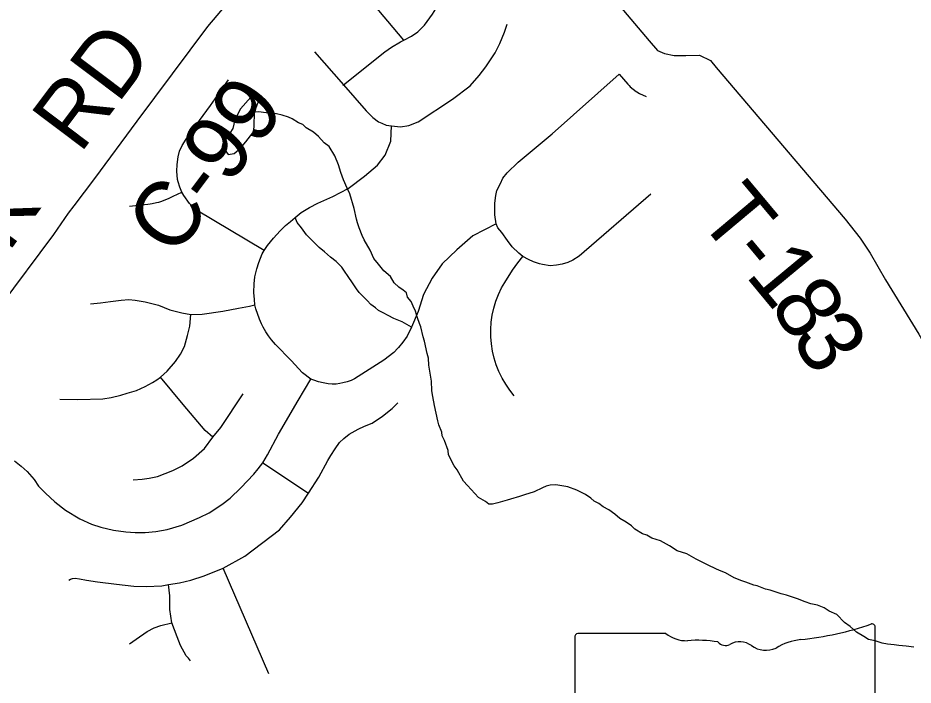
# Model space of a CAD drawing. Extents: x 0 to 34, y 0 to 22.
# Drawn here: x 3.321 to 4.106, y 17.969 to 18.554 of the extents above; entities that cross this region are included whole.
import ezdxf

# ---------------------------------------------------------------- set-up
doc = ezdxf.new("R2010")
doc.units = 0
for name, color, linetype in [('GM_X_County_Road', 7, 'Continuous'), ('GM_X_County_Road_Text', 7, 'Continuous'), ('GM_X_Minor_Lake', 7, 'Continuous'), ('GM_X_Minor_River', 7, 'Continuous'), ('GM_X_State_Shield', 7, 'Continuous'), ('GM_X_Township_Road', 7, 'Continuous'), ('GM_X_Township_Road_Text', 7, 'Continuous')]:
    doc.layers.add(name, color=color, linetype=linetype)

msp = doc.modelspace()

# ---------------------------------------------------------------- linework, layer by layer
at = {"layer": 'GM_X_County_Road'}
msp.add_lwpolyline([(3.28048, 18.24487), (3.28093, 18.24755), (3.28218, 18.25236), (3.28378, 18.25861), (3.28592, 18.26521), (3.28753, 18.27003), (3.28967, 18.27502), (3.29128, 18.27913), (3.29449, 18.28448), (3.29663, 18.28876), (3.29913, 18.29322), (3.30466, 18.30107), (3.35199, 18.36434), (3.36482, 18.38288), (3.36982, 18.38948), (3.38797, 18.4133), (3.42526, 18.46363), (3.48712, 18.54671), (3.50356, 18.56619), (3.51049, 18.57724)], dxfattribs=at)
at = {"layer": 'GM_X_Minor_Lake'}
for points in [[(3.5281, 18.47166), (3.53126, 18.48044), (3.52909, 18.48694), (3.52486, 18.48473), (3.51594, 18.47462), (3.51082, 18.46483), (3.50917, 18.45726), (3.50651, 18.45308), (3.50369, 18.44861), (3.50099, 18.44637), (3.49976, 18.44184), (3.50497, 18.43452), (3.5103, 18.43519), (3.51571, 18.44004), (3.52038, 18.44566)], [(3.52038, 18.44566), (3.52676, 18.45352), (3.52743, 18.45597), (3.52787, 18.45942), (3.5281, 18.47166)]]:
    msp.add_lwpolyline(points, dxfattribs=at)
at = {"layer": 'GM_X_Minor_River'}
for points in [[(3.68609, 18.21406), (3.68538, 18.21749), (3.68435, 18.2236), (3.68365, 18.22741), (3.68341, 18.2354), (3.68203, 18.24418), (3.68098, 18.24952), (3.68071, 18.25561), (3.67964, 18.25981), (3.67716, 18.27051), (3.67608, 18.27433), (3.67394, 18.28311), (3.67286, 18.28618), (3.67104, 18.29115), (3.66924, 18.29689), (3.66741, 18.30149), (3.66558, 18.30532), (3.66222, 18.30918), (3.66152, 18.313), (3.65852, 18.31533), (3.65476, 18.31806), (3.65065, 18.32194), (3.64732, 18.32732), (3.6417, 18.33236), (3.63686, 18.33815), (3.63276, 18.34317), (3.62946, 18.35045), (3.62429, 18.35967), (3.62246, 18.36351), (3.61991, 18.37002), (3.61846, 18.37461), (3.61775, 18.37766), (3.61563, 18.38721), (3.61166, 18.39983), (3.60947, 18.40482), (3.60617, 18.4121), (3.604, 18.4186), (3.60183, 18.42549), (3.59854, 18.43315), (3.59374, 18.4416), (3.58923, 18.44472), (3.58438, 18.45014), (3.57988, 18.45402), (3.57349, 18.45793), (3.57049, 18.46065), (3.56671, 18.46224), (3.56107, 18.46576), (3.55806, 18.46733), (3.55238, 18.46895), (3.54746, 18.47018), (3.54405, 18.47062), (3.53835, 18.4711), (3.53152, 18.47198), (3.5281, 18.47166)], [(4.10679, 18.00209), (4.09996, 18.00297), (4.09351, 18.00346), (4.08934, 18.00429), (4.08365, 18.00477), (4.07872, 18.00562), (4.07267, 18.00763), (4.06699, 18.00887), (4.06285, 18.0116), (4.05645, 18.01514), (4.05083, 18.02018), (4.04595, 18.02369), (4.03922, 18.03065), (4.03243, 18.03381), (4.02792, 18.03655), (4.02225, 18.03893), (4.01619, 18.04018), (4.01128, 18.04179), (4.00448, 18.04457), (3.99503, 18.04778), (3.99011, 18.049), (3.98066, 18.05221), (3.97649, 18.05304), (3.96931, 18.05583), (3.96629, 18.05665), (3.9591, 18.05905), (3.9557, 18.06025), (3.94891, 18.06304), (3.94137, 18.06735), (3.9376, 18.06894), (3.93344, 18.07053), (3.92553, 18.07447), (3.91912, 18.07763), (3.91572, 18.07921), (3.90744, 18.08392), (3.89912, 18.08672), (3.89235, 18.09103), (3.88444, 18.09535), (3.87688, 18.09776), (3.87236, 18.1005), (3.86858, 18.10171), (3.8618, 18.10563), (3.85881, 18.10873), (3.8543, 18.11185), (3.84865, 18.11499), (3.84416, 18.11887), (3.8389, 18.12277), (3.834, 18.12514), (3.83025, 18.12824), (3.8261, 18.13022), (3.8231, 18.13293), (3.81859, 18.13605), (3.81106, 18.13999), (3.80312, 18.14279), (3.79592, 18.14406), (3.79251, 18.1445), (3.78756, 18.1442), (3.78412, 18.1435), (3.78068, 18.14204), (3.77339, 18.13836), (3.76499, 18.13585), (3.76078, 18.1344), (3.75275, 18.13188), (3.7497, 18.13117), (3.74167, 18.12865), (3.73709, 18.12759), (3.73367, 18.12765), (3.73067, 18.12998), (3.72465, 18.13351), (3.71494, 18.14395), (3.71158, 18.14781), (3.70605, 18.1578), (3.70344, 18.16127), (3.69828, 18.17087), (3.69797, 18.17468), (3.69469, 18.18348), (3.69287, 18.1877), (3.69254, 18.19075), (3.68998, 18.19725), (3.6889, 18.2007), (3.6875, 18.20757), (3.68609, 18.21406)]]:
    msp.add_lwpolyline(points, dxfattribs=at)
at = {"layer": 'GM_X_State_Shield'}
for p, q in [((3.88895, 18.01415), (3.81173, 18.01415)), ((4.0728, 17.91443), (4.0728, 18.01911)), ((3.80914, 18.01071), (3.80914, 17.81059))]:
    msp.add_line(p, q, dxfattribs=at)
for centre, radius, start, end in [((3.97888, 18.28698), 0.27962, 275.84447, 288.90645), ((4.06988, 18.01955), 0.00294, 351.86209, 97.738), ((3.81216, 18.01113), 0.00305, 98.1301, 188.1301), ((3.90734, 18.03738), 0.02963, 231.61951, 271.11188), ((3.91716, 17.9018), 0.10636, 80.48669, 94.98827), ((3.94131, 18.01217), 0.00855, 219.79206, 297.10237), ((3.95386, 17.98904), 0.01777, 54.46668, 119.14113), ((4.01455, 17.95303), 0.05625, 97.34618, 120.76885), ((3.97679, 18.02077), 0.02138, 233.85621, 294.82819)]:
    msp.add_arc(centre, radius, start, end, dxfattribs=at)
at = {"layer": 'GM_X_Township_Road'}
for p, q in [((3.65907, 18.53492), (3.62723, 18.57296)), ((3.5809, 18.52458), (3.60627, 18.4955)), ((3.53531, 18.16382), (3.57552, 18.13728)), ((3.54078, 17.97867), (3.50055, 18.07132)), ((3.47209, 17.99005), (3.47016, 17.99232))]:
    msp.add_line(p, q, dxfattribs=at)
for points in [[(3.74221, 18.69056), (3.87434, 18.53429), (3.88179, 18.52559), (3.888, 18.52311), (3.89649, 18.52145), (3.90663, 18.52145), (3.91864, 18.52166), (3.92816, 18.51689), (3.93313, 18.51089), (4.04636, 18.37758), (4.05961, 18.36102), (4.06831, 18.34777), (4.08176, 18.32438), (4.11095, 18.27676), (4.12193, 18.25775), (4.1353, 18.2338), (4.14366, 18.21782), (4.15388, 18.20055), (4.16056, 18.19219), (4.16762, 18.18421), (4.17319, 18.17399), (4.18062, 18.15486), (4.18415, 18.14613), (4.18898, 18.13684)], [(3.65907, 18.53492), (3.66594, 18.53835), (3.67139, 18.54213), (3.67734, 18.54791), (3.68436, 18.5575), (3.68867, 18.56474), (3.69091, 18.571), (3.69201, 18.57755), (3.6915, 18.58749), (3.68906, 18.59542), (3.68684, 18.59988), (3.68399, 18.60397), (3.67156, 18.61849)], [(3.64845, 18.45956), (3.65619, 18.45865), (3.66365, 18.45978), (3.6718, 18.46317), (3.70187, 18.48307), (3.71725, 18.49483), (3.72517, 18.50365), (3.73105, 18.51134), (3.73942, 18.52378), (3.74326, 18.53192), (3.74756, 18.54187), (3.74982, 18.54888)], [(3.60564, 18.49499), (3.60627, 18.4955), (3.64239, 18.5246), (3.64834, 18.52858), (3.65636, 18.53338), (3.65907, 18.53492)], [(3.4644, 18.40136), (3.46249, 18.40579), (3.461, 18.41038), (3.46065, 18.41238), (3.45997, 18.41968), (3.46014, 18.42576), (3.46112, 18.43234), (3.46244, 18.43743), (3.46458, 18.44237), (3.46803, 18.44795), (3.4705, 18.45124), (3.47674, 18.45979), (3.4894, 18.47755), (3.49762, 18.48922), (3.50519, 18.50007)], [(3.87598, 18.39975), (3.81311, 18.34514), (3.80743, 18.3416), (3.80318, 18.33971), (3.79798, 18.33829), (3.79301, 18.33734), (3.78758, 18.33663), (3.78072, 18.33782), (3.77812, 18.33853), (3.77292, 18.34018), (3.76843, 18.34231), (3.76346, 18.34491), (3.75992, 18.34774), (3.75424, 18.35342), (3.74999, 18.35909), (3.74503, 18.36595), (3.74172, 18.3702), (3.74025, 18.37375), (3.73912, 18.38155), (3.73912, 18.39171), (3.73983, 18.39833), (3.74077, 18.40282), (3.74384, 18.40897), (3.74597, 18.4137), (3.74975, 18.41842), (3.75945, 18.42764), (3.78923, 18.45246), (3.84805, 18.50481)], [(3.84805, 18.50481), (3.85182, 18.50055), (3.85559, 18.49628), (3.85673, 18.49509), (3.85787, 18.49389), (3.86035, 18.49172), (3.86302, 18.48978), (3.86364, 18.4894), (3.86585, 18.48808), (3.87191, 18.48546)], [(3.60627, 18.4955), (3.62617, 18.47269), (3.63191, 18.4668), (3.63697, 18.46317), (3.63991, 18.46181), (3.64375, 18.46023), (3.64845, 18.45956)], [(3.74025, 18.37375), (3.71963, 18.3631), (3.70566, 18.3508), (3.69268, 18.33849), (3.68404, 18.32585), (3.67639, 18.31155), (3.67173, 18.29658), (3.66593, 18.283), (3.66194, 18.27511), (3.65841, 18.26969), (3.65454, 18.26505), (3.65393, 18.26441), (3.65044, 18.26073), (3.64148, 18.25387), (3.61583, 18.23761), (3.61306, 18.23606), (3.6093, 18.23485), (3.60576, 18.23396), (3.60311, 18.23341), (3.59968, 18.23297), (3.59625, 18.23297), (3.59289, 18.23319), (3.58835, 18.23408), (3.58415, 18.23507), (3.58028, 18.23629), (3.5774, 18.23717), (3.5701, 18.24281), (3.56015, 18.25354), (3.54654, 18.26781), (3.543, 18.27179), (3.54035, 18.27544), (3.53802, 18.27876), (3.53559, 18.28296), (3.53429, 18.28578), (3.53252, 18.28988), (3.52942, 18.29905), (3.52854, 18.30259), (3.52809, 18.30724), (3.52765, 18.31332), (3.52776, 18.32095), (3.52854, 18.32715), (3.5302, 18.33412), (3.53185, 18.33982), (3.53495, 18.34734), (3.5365, 18.3501), (3.53961, 18.3546), (3.54475, 18.36117), (3.55051, 18.36755), (3.55525, 18.37202), (3.55969, 18.37579), (3.56368, 18.37909), (3.56905, 18.38347), (3.57628, 18.38807), (3.58359, 18.39171), (3.59689, 18.3977), (3.6102, 18.40468), (3.6245, 18.41532), (3.63614, 18.42497), (3.64279, 18.43395), (3.64778, 18.44626), (3.64845, 18.45956)], [(3.41845, 18.38916), (3.42877, 18.39039), (3.43451, 18.39095), (3.43643, 18.3912), (3.43836, 18.39146), (3.44218, 18.39223), (3.44405, 18.39275), (3.44593, 18.39327), (3.4496, 18.39455), (3.45317, 18.39609), (3.45676, 18.39777), (3.4644, 18.40136)], [(3.5365, 18.3501), (3.47733, 18.38553), (3.47118, 18.39149), (3.46609, 18.39837), (3.4644, 18.40136)], [(3.66593, 18.283), (3.65776, 18.2876), (3.65044, 18.2906), (3.64545, 18.29326), (3.64113, 18.29558), (3.63681, 18.29758), (3.63415, 18.29991), (3.63015, 18.3029), (3.62683, 18.30623), (3.62383, 18.30955), (3.61984, 18.31321), (3.61751, 18.31654), (3.61419, 18.32186), (3.6102, 18.32752), (3.6072, 18.33217), (3.60488, 18.3355), (3.60222, 18.33816), (3.59989, 18.34049), (3.5949, 18.34448), (3.58958, 18.34913), (3.58492, 18.35279), (3.57893, 18.35878), (3.57361, 18.3641), (3.56929, 18.37009), (3.56563, 18.37475), (3.56368, 18.37909)], [(3.74763, 18.32221), (3.75448, 18.33285), (3.75921, 18.33947), (3.76346, 18.34491)], [(3.75608, 18.22267), (3.75213, 18.2276), (3.74856, 18.23282), (3.74538, 18.23828), (3.74262, 18.24396), (3.74029, 18.24983), (3.73839, 18.25586), (3.73695, 18.26201), (3.73597, 18.26826), (3.73546, 18.27455), (3.73541, 18.28087), (3.73583, 18.28718), (3.73671, 18.29343), (3.73806, 18.29961), (3.73986, 18.30566), (3.74211, 18.31157), (3.74478, 18.3173), (3.74763, 18.32221)], [(3.38413, 18.30353), (3.39297, 18.30436), (3.40181, 18.30546), (3.4112, 18.30657), (3.41782, 18.30712), (3.42334, 18.30657), (3.43218, 18.30519), (3.44378, 18.30215), (3.45372, 18.29828), (3.46449, 18.29552), (3.47222, 18.29414), (3.48216, 18.29442), (3.50038, 18.2969), (3.51419, 18.29966), (3.52385, 18.30132), (3.52854, 18.30259)], [(3.35735, 18.21986), (3.37309, 18.21959), (3.3949, 18.22014), (3.40236, 18.22124), (3.41092, 18.22318), (3.41644, 18.22511), (3.42445, 18.22732), (3.43218, 18.23091), (3.43853, 18.2345), (3.4424, 18.23671), (3.44571, 18.23919), (3.45151, 18.24444), (3.45869, 18.25272), (3.46311, 18.25935), (3.4667, 18.26598), (3.46946, 18.27564), (3.47139, 18.28392), (3.47222, 18.29414)], [(3.31759, 18.16564), (3.32337, 18.16101), (3.32873, 18.15624), (3.3348, 18.1493), (3.33871, 18.14351), (3.3446, 18.1373), (3.353, 18.12951), (3.36214, 18.12239), (3.37473, 18.11487), (3.3851, 18.10999), (3.39334, 18.10739), (3.40449, 18.10464), (3.41519, 18.10319), (3.42343, 18.10261), (3.43225, 18.10276), (3.44151, 18.10348), (3.4515, 18.10536), (3.46422, 18.10913), (3.47999, 18.11577), (3.48836, 18.12012), (3.49956, 18.12728), (3.50673, 18.13299), (3.51598, 18.14182), (3.52749, 18.15402), (3.53142, 18.15859), (3.53531, 18.16382), (3.53945, 18.17096), (3.54926, 18.18903), (3.56647, 18.21854), (3.5774, 18.23717)], [(3.49155, 18.18645), (3.48492, 18.19225), (3.46559, 18.21517), (3.44571, 18.23919)], [(3.42169, 18.1489), (3.42942, 18.14945), (3.43577, 18.15028), (3.44295, 18.15194), (3.44985, 18.15442), (3.45648, 18.15718), (3.46476, 18.16132), (3.4747, 18.16795), (3.48409, 18.17651), (3.49155, 18.18645), (3.49845, 18.19474), (3.51806, 18.22456)], [(3.57552, 18.13728), (3.5846, 18.15138), (3.59233, 18.16602), (3.5951, 18.17044), (3.59896, 18.17624), (3.60255, 18.18176), (3.60642, 18.18535), (3.61111, 18.18894), (3.61912, 18.19336), (3.62464, 18.19612), (3.63127, 18.1986), (3.64038, 18.20468), (3.64894, 18.21158), (3.65391, 18.21655)], [(3.50055, 18.07132), (3.51956, 18.08185), (3.55009, 18.10499), (3.55975, 18.11632), (3.56997, 18.12874), (3.57552, 18.13728)], [(3.45251, 18.05699), (3.4624, 18.05866), (3.47223, 18.06097), (3.48381, 18.06458), (3.50055, 18.07132)], [(3.36512, 18.06084), (3.36668, 18.06182), (3.36835, 18.06248), (3.37073, 18.06272), (3.37452, 18.06221), (3.38055, 18.06078), (3.39032, 18.05945), (3.40713, 18.05737), (3.42209, 18.0557), (3.43297, 18.05525), (3.44672, 18.05601), (3.45251, 18.05699)], [(3.47016, 17.99232), (3.46824, 17.99459), (3.46321, 18.00356), (3.46025, 18.01106), (3.45552, 18.02339), (3.45394, 18.03503), (3.45388, 18.04728), (3.45251, 18.05699)], [(3.41833, 18.00494), (3.42415, 18.00899), (3.43401, 18.01579), (3.44013, 18.01895), (3.44595, 18.02102), (3.45552, 18.02339)]]:
    msp.add_lwpolyline(points, dxfattribs=at)

# ---------------------------------------------------------------- texts
at = {"layer": 'GM_X_County_Road_Text'}
for s, height, rotation, p in [('RD', 0.056818, 53.03133, (3.37496, 18.43422)), ('C-99', 0.056818, 53.26709, (3.45776, 18.34257)), ('K', 0.05682, 53.92789, (3.31199, 18.34768))]:
    msp.add_text(s, height=height, rotation=rotation, dxfattribs=at).set_placement(p)
at = {"layer": 'GM_X_Township_Road_Text'}
for s, rotation, p in [('T', 309.96634, (3.91581, 18.3788)), ('-', 309.91551, (3.94311, 18.34623)), ('1', 309.62701, (3.95803, 18.32839)), ('8', 303.02758, (3.97933, 18.30283)), ('3', 301.71524, (3.99822, 18.27377))]:
    msp.add_text(s, height=0.05682, rotation=rotation, dxfattribs=at).set_placement(p)

doc.saveas('drawing.dxf')
